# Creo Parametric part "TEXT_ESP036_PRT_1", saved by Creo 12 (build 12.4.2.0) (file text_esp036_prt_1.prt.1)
Units: Custom; MM, KILOGRAM, SECS

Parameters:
  PTC_WM_ITERATION = "0"
  PTC_WM_VERSION = "-.0"
  PTC_WM_LIFECYCLE_STATE = "In Work"
  PTC_WM_LIFECYCLE = "MO_CADDocument"
  PTC_WM_CREATED_BY = "Maximilian Roepper (Z0017RMS: MO)"
  PTC_WM_CREATED_ON = "18-Sep-26 11:36:42 AM"
  PTC_WM_MODIFIED_BY = "Maximilian Roepper (Z0017RMS: MO)"
  PTC_WM_MODIFIED_ON = "18-Sep-26 11:36:46 AM"
  PDMLINKNUMBER = "PDM000071454855"
  PTC_WM_NAME = "text_esp036_prt_1.prt"
  PTC_WM_NUMBER = "PDM000071454855"

Other parameters: WEIGHT, WEIGHT_FACTOR, WEIGHT_ADD, _MASS_TEMP, _DIFF_TEMP, MC_ERRORS, SUPPLIER

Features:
  1. coordinate system
  2. datum plane "PRT_YZ"
  3. datum plane "PRT_XY"
  4. datum plane "PRT_XZ"
  5. coordinate system
  6. datum axis
  7. datum axis
  8. datum axis
  9. coordinate system
  10. imported feature
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
Other named items: PRT, SIEMENS_MO, DRW_VIEW_ORG, PRT_X, PRT_Y, PRT_Z, CS0, ROUGH_GROB

Layers: 00_STD_CSYS-KSYS, 01_STD_PLANES-EBENEN, 02_STD_AXES-ACHSEN, 03_STD_CSYS-KSYS, 24_IMPORT_FEAT-IMPORT_KE

Surfaces: 15 plane, 5 tabulated cylinder, 1 cylinder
